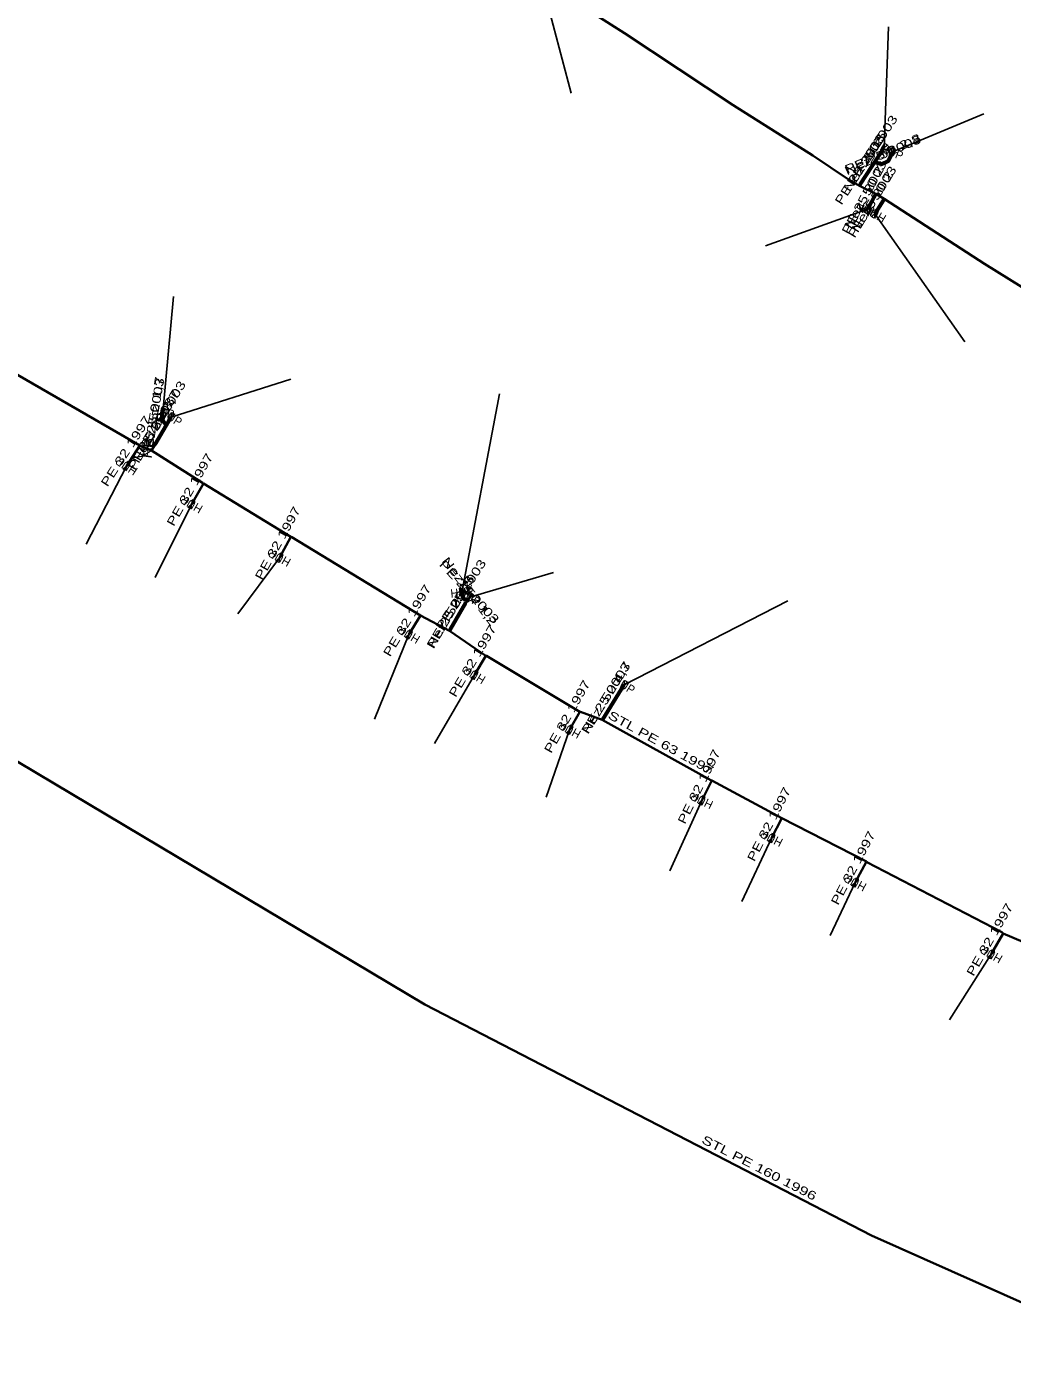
# Model space of a CAD drawing. Extents: x -737484 to -734496, y -1033882 to -1030666.
# Drawn here: x -736166.9 to -736052.2, y -1032940.7 to -1032786.1 of the extents above; entities that cross this region are included whole.
import ezdxf
from ezdxf.enums import TextEntityAlignment as Align

# ---------------------------------------------------------------- set-up
doc = ezdxf.new("R2010")
doc.units = 0
doc.header["$LTSCALE"] = 0.4
for name, color, linetype, lineweight in [('1', 7, 'Continuous', 13), ('18', 7, 'Continuous', 60), ('22', 7, 'Continuous', 25), ('5', 7, 'Continuous', 35), ('7', 7, 'Continuous', 35)]:
    doc.layers.add(name, color=color, linetype=linetype, lineweight=lineweight)
doc.layers.add('2', color=7, linetype='Continuous')

msp = doc.modelspace()

# ---------------------------------------------------------------- linework, layer by layer
at = {"layer": '1'}
for points in [[(-736067.06, -1032799.659), (-736066.724, -1032799.877), (-736067.605, -1032800.498), (-736067.269, -1032800.716)], [(-736066.26, -1032800.14), (-736065.887, -1032800.283), (-736066.618, -1032801.074), (-736066.245, -1032801.217)], [(-736069.134, -1032807.833), (-736069.487, -1032807.645), (-736068.664, -1032806.95), (-736069.017, -1032806.762)], [(-736068.313, -1032808.366), (-736068.655, -1032808.16), (-736067.798, -1032807.509), (-736068.14, -1032807.303)], [(-736151.121, -1032830.41), (-736150.727, -1032830.48), (-736151.294, -1032831.395), (-736150.9, -1032831.465)], [(-736149.958, -1032830.935), (-736149.619, -1032831.147), (-736150.488, -1032831.784), (-736150.149, -1032831.996)], [(-736155.35, -1032837.696), (-736155.686, -1032837.478), (-736154.805, -1032836.857), (-736155.141, -1032836.639)], [(-736147.765, -1032842.149), (-736148.112, -1032841.949), (-736147.265, -1032841.282), (-736147.612, -1032841.082)], [(-736137.516, -1032848.358), (-736137.866, -1032848.164), (-736137.031, -1032847.483), (-736137.381, -1032847.289)], [(-736116.494, -1032851.378), (-736116.096, -1032851.336), (-736116.389, -1032852.373), (-736115.991, -1032852.331)], [(-736115.235, -1032851.859), (-736114.899, -1032852.077), (-736115.78, -1032852.698), (-736115.444, -1032852.916)], [(-736122.503, -1032857.28), (-736122.845, -1032857.074), (-736121.988, -1032856.423), (-736122.33, -1032856.217)], [(-736114.889, -1032861.978), (-736115.231, -1032861.772), (-736114.374, -1032861.121), (-736114.716, -1032860.915)], [(-736097.304, -1032862.077), (-736096.965, -1032862.289), (-736097.834, -1032862.926), (-736097.495, -1032863.138)], [(-736103.792, -1032868.354), (-736104.142, -1032868.16), (-736103.307, -1032867.479), (-736103.657, -1032867.285)], [(-736088.396, -1032876.571), (-736088.755, -1032876.395), (-736087.958, -1032875.672), (-736088.317, -1032875.496)], [(-736080.302, -1032880.963), (-736080.659, -1032880.781), (-736079.848, -1032880.072), (-736080.205, -1032879.89)], [(-736070.586, -1032886.123), (-736070.939, -1032885.935), (-736070.116, -1032885.24), (-736070.469, -1032885.052)], [(-736054.777, -1032894.45), (-736055.124, -1032894.25), (-736054.277, -1032893.583), (-736054.624, -1032893.383)]]:
    msp.add_lwpolyline(points, close=True, dxfattribs=at)
at = {"layer": '18'}
for p, q in [((-736069.929, -1032804.425), (-736067.165, -1032800.187)), ((-736068.135, -1032805.535), (-736069.099, -1032807.31)), ((-736067.174, -1032806.114), (-736068.226, -1032807.834)), ((-736151.908, -1032834.644), (-736150.053, -1032831.465)), ((-736117.624, -1032856.19), (-736115.784, -1032853.048)), ((-736099.882, -1032866.613), (-736097.399, -1032862.607))]:
    msp.add_line(p, q, dxfattribs=at)
for points in [[(-736068.221, -1032801.824), (-736067.44, -1032802.078), (-736066.679, -1032801.729), (-736066.207, -1032800.69)], [(-736150.651, -1032832.381), (-736151.142, -1032831.752), (-736151.004, -1032830.823)], [(-736115.78, -1032852.847), (-736116.192, -1032852.301), (-736116.264, -1032851.721)]]:
    msp.add_lwpolyline(points, dxfattribs=at)
at = {"layer": '22'}
for p, q in [((-736106.34, -1032783.281), (-736103.566, -1032793.829)), ((-736067.165, -1032800.188), (-736066.638, -1032786.1)), ((-736066.253, -1032800.679), (-736055.551, -1032796.24)), ((-736069.076, -1032807.298), (-736080.951, -1032811.577)), ((-736068.227, -1032807.835), (-736057.763, -1032822.742)), ((-736151.011, -1032830.938), (-736149.768, -1032817.44)), ((-736150.054, -1032831.466), (-736136.121, -1032827.073)), ((-736116.243, -1032851.855), (-736111.868, -1032828.753)), ((-736155.247, -1032837.169), (-736159.924, -1032846.253)), ((-736147.69, -1032841.617), (-736151.922, -1032850.114)), ((-736137.45, -1032847.824), (-736142.319, -1032854.352)), ((-736115.34, -1032852.388), (-736105.616, -1032849.55)), ((-736097.4, -1032862.608), (-736078.351, -1032852.82)), ((-736122.418, -1032856.749), (-736126.408, -1032866.595)), ((-736114.803, -1032861.447), (-736119.441, -1032869.42)), ((-736103.726, -1032867.821), (-736106.449, -1032875.636)), ((-736088.357, -1032876.035), (-736092.092, -1032884.207)), ((-736080.254, -1032880.428), (-736083.713, -1032887.785)), ((-736070.528, -1032885.589), (-736073.451, -1032891.741)), ((-736054.701, -1032893.917), (-736059.565, -1032901.535))]:
    msp.add_line(p, q, dxfattribs=at)
at = {"layer": '5'}
for points in [[(-736164.978, -1032743.294), (-736163.22, -1032744.622), (-736144.295, -1032756.82), (-736143.663, -1032757.201), (-736143.285, -1032757.399), (-736123.669, -1032770.149), (-736106.324, -1032781.201), (-736106.054, -1032781.318), (-736105.301, -1032781.762), (-736097.333, -1032786.842), (-736084.708, -1032795.224), (-736075.443, -1032801.061), (-736071.322, -1032803.858), (-736070.031, -1032804.587), (-736068.124, -1032805.517), (-736067.175, -1032806.115), (-736055.501, -1032813.666), (-736043.698, -1032820.973), (-736041.939, -1032821.797)], [(-736169.66, -1032825.54), (-736153.7, -1032834.78), (-736153.61, -1032834.82), (-736152.348, -1032835.366), (-736146.42, -1032839.12), (-736146.31, -1032839.18), (-736136.12, -1032845.4), (-736136.02, -1032845.44), (-736121.08, -1032854.53), (-736117.708, -1032856.327), (-736113.48, -1032859.21), (-736113.39, -1032859.22), (-736102.55, -1032865.72), (-736102.46, -1032865.72), (-736099.95, -1032866.681), (-736087.32, -1032873.66), (-736087.21, -1032873.71), (-736079.06, -1032878.09), (-736069.23, -1032883.12), (-736069.17, -1032883.19), (-736053.48, -1032891.33), (-736053.32, -1032891.49), (-736045.452, -1032894.832)], [(-736235.45, -1032828.77), (-736180.2, -1032864.22), (-736120.57, -1032899.77), (-736068.64, -1032926.61), (-736000.29, -1032957.08), (-736038.27, -1033017.25), (-736040.52, -1033020.79), (-736047.44, -1033030.09), (-736048.2, -1033031.22)]]:
    msp.add_lwpolyline(points, dxfattribs=at)
at = {"layer": '7'}
for p, q in [((-736068.253, -1032801.832), (-736067.165, -1032800.188)), ((-736068.124, -1032805.517), (-736069.076, -1032807.298)), ((-736067.175, -1032806.115), (-736068.227, -1032807.835)), ((-736150.637, -1032832.407), (-736150.054, -1032831.466)), ((-736153.7, -1032834.78), (-736155.246, -1032837.168)), ((-736146.31, -1032839.18), (-736147.689, -1032841.616)), ((-736136.12, -1032845.4), (-736137.449, -1032847.824)), ((-736115.695, -1032852.936), (-736115.34, -1032852.388)), ((-736121.08, -1032854.53), (-736122.417, -1032856.749)), ((-736113.48, -1032859.21), (-736114.803, -1032861.447)), ((-736102.55, -1032865.72), (-736103.725, -1032867.82)), ((-736087.21, -1032873.71), (-736088.357, -1032876.034)), ((-736079.06, -1032878.09), (-736080.254, -1032880.427)), ((-736069.23, -1032883.12), (-736070.528, -1032885.588)), ((-736053.32, -1032891.49), (-736054.701, -1032893.917))]:
    msp.add_line(p, q, dxfattribs=at)
for points in [[(-736068.253, -1032801.832), (-736067.497, -1032802.08), (-736066.649, -1032801.724), (-736066.253, -1032800.679)], [(-736070.031, -1032804.587), (-736069.93, -1032804.426), (-736068.253, -1032801.832)], [(-736150.637, -1032832.407), (-736151.154, -1032831.759), (-736151.011, -1032830.938)], [(-736152.348, -1032835.366), (-736151.909, -1032834.645), (-736150.637, -1032832.407)], [(-736115.695, -1032852.936), (-736116.187, -1032852.406), (-736116.243, -1032851.855)], [(-736117.708, -1032856.327), (-736117.625, -1032856.191), (-736115.785, -1032853.049), (-736115.695, -1032852.936)], [(-736099.95, -1032866.681), (-736099.882, -1032866.614), (-736097.4, -1032862.608)]]:
    msp.add_lwpolyline(points, dxfattribs=at)

# ---------------------------------------------------------------- texts
at = {"layer": '18', "width": 1.4}
for s, rotation, p in [('Nez. 50 5', 56.888, (-736068.9656, -1032802.0321)), ('Nez. 50 2,8', 24.637, (-736067.1219, -1032801.3817)), ('Nez. 50 2', 61.494, (-736069.0553, -1032806.1836)), ('Nez. 50 2', 58.549, (-736068.1259, -1032806.7124)), ('Nez. 50 1,7', 81.551, (-736151.626, -1032831.6085)), ('Nez. 50 3,7', 59.736, (-736151.4116, -1032832.802)), ('Nez. 50 1,2', 307.037, (-736115.7625, -1032852.0388)), ('Nez. 50 4,5', 59.646, (-736117.1351, -1032854.3657)), ('Nez. 50 4,7', 58.209, (-736099.0654, -1032864.3464))]:
    msp.add_text(s, height=1, rotation=rotation, dxfattribs=at).set_placement(p, align=Align.CENTER)
at = {"layer": '2', "width": 0.95}
for rotation, p in [(327, (-736067.4368, -1032800.6069)), (339, (-736066.4317, -1032801.1453)), (152, (-736068.8408, -1032806.856)), (149, (-736067.969, -1032807.4058)), (350, (-736151.0973, -1032831.4304)), (328, (-736150.3185, -1032831.8893)), (147, (-736154.9732, -1032836.7481)), (150, (-736147.4385, -1032841.1829)), (151, (-736137.2061, -1032847.3859)), (6, (-736116.1908, -1032852.3513)), (327, (-736115.6118, -1032852.8069)), (149, (-736122.159, -1032856.3198)), (149, (-736114.545, -1032861.0178)), (328, (-736097.6645, -1032863.0313)), (151, (-736103.4821, -1032867.3819)), (154, (-736088.1373, -1032875.5845)), (153, (-736080.0265, -1032879.9805)), (152, (-736070.2928, -1032885.146)), (150, (-736054.4505, -1032893.4839))]:
    msp.add_text('HUP', height=1, rotation=rotation, dxfattribs=at).set_placement(p, align=Align.CENTER)
at = {"layer": '5', "width": 1.4}
for s, rotation, p in [('STL PE 63 1997', 331.076, (-736093.3528, -1032869.7547)), ('STL PE 160 1996', 332.668, (-736081.9076, -1032919.1892))]:
    msp.add_text(s, height=1, rotation=rotation, dxfattribs=at).set_placement(p, align=Align.CENTER)
at = {"layer": '7', "width": 1.35}
for s, rotation, p in [('PE 25 2003', 56.503, (-736068.1258, -1032800.7334)), ('PE 25 2003', 57.118, (-736069.5626, -1032802.937)), ('PE 25 2003', 22.773, (-736067.117, -1032801.3784)), ('PE 25 2003', 61.874, (-736069.0407, -1032806.1717)), ('PE 25 2003', 58.549, (-736068.1269, -1032806.7139)), ('PE 25 2003', 80.119, (-736151.6455, -1032831.6703)), ('PE 25 2003', 58.22, (-736150.7697, -1032831.6728)), ('PE 25 2003', 60.388, (-736151.9155, -1032833.6456)), ('PE 32 1997', 57.081, (-736154.8921, -1032835.7017)), ('PE 32 1997', 60.486, (-736147.4339, -1032840.1508)), ('PE 32 1997', 61.265, (-736137.2228, -1032846.3709)), ('PE 25 2003', 57.064, (-736115.9368, -1032852.3893)), ('PE 25 2003', 312.871, (-736115.7623, -1032852.1268)), ('PE 25 2003', 59.646, (-736117.1401, -1032854.3732)), ('PE 32 1997', 58.93, (-736122.1764, -1032855.3805)), ('PE 32 1997', 59.399, (-736114.5712, -1032860.0735)), ('PE 25 2003', 58.219, (-736099.0907, -1032864.3878)), ('PE 32 1997', 60.772, (-736103.5738, -1032866.5251)), ('PE 32 1997', 63.732, (-736088.2309, -1032874.6503)), ('PE 32 1997', 62.937, (-736080.1016, -1032879.0305)), ('PE 32 1997', 62.259, (-736070.3212, -1032884.1207)), ('PE 32 1997', 60.359, (-736054.4445, -1032892.4558))]:
    msp.add_text(s, height=1, rotation=rotation, dxfattribs=at).set_placement(p, align=Align.CENTER)

doc.saveas('drawing.dxf')
